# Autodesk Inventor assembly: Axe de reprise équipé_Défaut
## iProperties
Shininess: 64.0
Length Units: 11269
Angle Units: 11279
Time Units: 11290
Mass Units: 11283
Length Display Precision: 3
Angle Display Precision: 2
Compacted: True
Created: 2006-01
Part Number: Axe de reprise équipé_Défaut
Document SubType Name: Assembly
Designer: riri
Density: 0.0
Volumn: 0.0
Area: 0.0
PropertySet Name: Model Information
Control State: 0
Master: False
Checked Out: False
Author: riri
